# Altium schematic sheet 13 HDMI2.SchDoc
size 297 x 209 mm
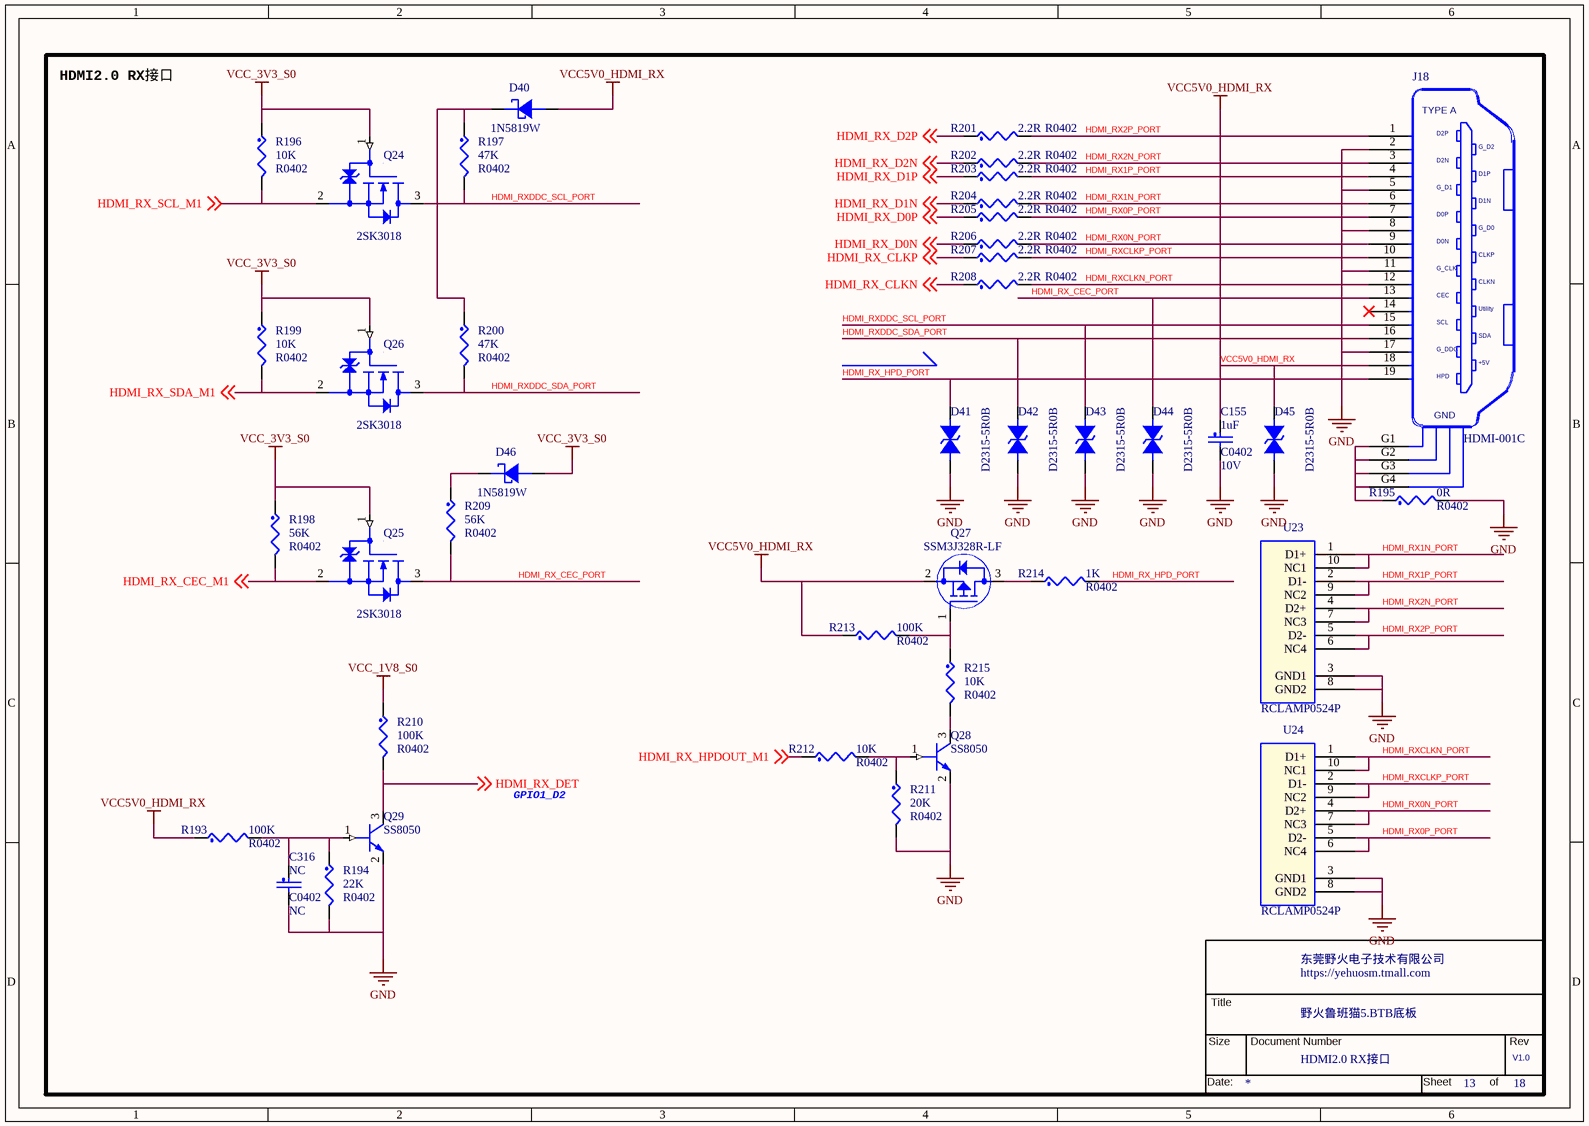
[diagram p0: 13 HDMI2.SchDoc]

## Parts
*  Doc: HDMI2.0 RX接口  RevCode: V1.0  Title: 野火鲁班猫5.BTB底板  OrgName: 东莞野火电子技术有限公司  Page Number: 13  Page Count: 18  (hidden comment: TitleBlock_YHSCH)  (graphical)
C155  1uF  Voltage: 10V  [C0402]
C316  NC  [C0402]
D40  1N5819W  [SOD-123]
D41  D2315-5R0B  [D0603/SMD]
D42  D2315-5R0B  [D0603/SMD]
D43  D2315-5R0B  [D0603/SMD]
D44  D2315-5R0B  [D0603/SMD]
D45  D2315-5R0B  [D0603/SMD]
D46  1N5819W  [SOD-123]
J18  HDMI-001C  [HDMI-SMD]
Q24  2SK3018  [SOT23]
Q25  2SK3018  [SOT23]
Q26  2SK3018  [SOT23]
Q27  SSM3J328R-LF  [SOT23]
Q28  SS8050  [SOT23]
Q29  SS8050  [SOT23]
R193  100K  [R0402]
R194  22K  [R0402]
R195  0R  [R0402]
R196  10K  [R0402]
R197  47K  [R0402]
R198  56K  [R0402]
R199  10K  [R0402]
R200  47K  [R0402]
R201  2.2R  [R0402]
R202  2.2R  [R0402]
R203  2.2R  [R0402]
R204  2.2R  [R0402]
R205  2.2R  [R0402]
R206  2.2R  [R0402]
R207  2.2R  [R0402]
R208  2.2R  [R0402]
R209  56K  [R0402]
R210  100K  [R0402]
R211  20K  [R0402]
R212  10K  [R0402]
R213  100K  [R0402]
R214  1K  [R0402]
R215  10K  [R0402]
U23  RCLAMP0524P  [USON_10]
U24  RCLAMP0524P  [USON_10]

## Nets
GND: C155.2 C316.2 D41.1 D42.1 D43.1 D44.1 D45.1 J18.2 J18.5 J18.8 J18.11 J18.17 Q28.2(EMITTER) Q29.2(EMITTER) R194.2 R195.2 R211.2 U23.3(GND1) U23.8(GND2) U24.3(GND1) U24.8(GND2)
VCC5V0_HDMI_RX: C155.1 D40.2 D45.2 J18.18 Q27.2(SOURCE) R193.1 R213.1
VCC_1V8_S0: R210.1
VCC_3V3_S0: D46.2 Q24.1(GATE) Q25.1(GATE) Q26.1(GATE) R196.1 R198.1 R199.1
HDMI_RX0N_PORT: J18.9 R206.2 U24.4(D2+) U24.7(NC3)
HDMI_RX0P_PORT: J18.7 R205.2 U24.5(D2-) U24.6(NC4)
HDMI_RX1N_PORT: J18.6 R204.2 U23.1(D1+) U23.10(NC1)
HDMI_RX1P_PORT: J18.4 R203.2 U23.2(D1-) U23.9(NC2)
HDMI_RX2N_PORT: J18.3 R202.2 U23.4(D2+) U23.7(NC3)
HDMI_RX2P_PORT: J18.1 R201.2 U23.5(D2-) U23.6(NC4)
HDMI_RX_CEC_M1: Q25.2(SOURCE) R198.2 ; off-sheet HDMI_RX_CEC_M1
HDMI_RX_CEC_PORT: D44.2 J18.13 Q25.3(DRAIN) R209.2
HDMI_RX_CLKN: R208.1 ; off-sheet HDMI_RX_CLKN
HDMI_RX_CLKP: R207.1 ; off-sheet HDMI_RX_CLKP
HDMI_RX_D0N: R206.1 ; off-sheet HDMI_RX_D0N
HDMI_RX_D0P: R205.1 ; off-sheet HDMI_RX_D0P
HDMI_RX_D1N: R204.1 ; off-sheet HDMI_RX_D1N
HDMI_RX_D1P: R203.1 ; off-sheet HDMI_RX_D1P
HDMI_RX_D2N: R202.1 ; off-sheet HDMI_RX_D2N
HDMI_RX_D2P: R201.1 ; off-sheet HDMI_RX_D2P
HDMI_RX_DET: Q29.3(COLLECTOR) R210.2 ; off-sheet HDMI_RX_DET
HDMI_RX_HPD_PORT: D41.2 J18.19 R214.2
HDMI_RX_HPDOUT_M1: R212.1 ; off-sheet HDMI_RX_HPDOUT_M1
HDMI_RX_SCL_M1: Q24.2(SOURCE) R196.2 ; off-sheet HDMI_RX_SCL_M1
HDMI_RX_SDA_M1: Q26.2(SOURCE) R199.2 ; off-sheet HDMI_RX_SDA_M1
HDMI_RXCLKN_PORT: J18.12 R208.2 U24.1(D1+) U24.10(NC1)
HDMI_RXCLKP_PORT: J18.10 R207.2 U24.2(D1-) U24.9(NC2)
HDMI_RXDDC_SCL_PORT: D43.2 J18.15 Q24.3(DRAIN) R197.2
HDMI_RXDDC_SDA_PORT: D42.2 J18.16 Q26.3(DRAIN) R200.2
NetC316_1: C316.1 Q29.1(BASE) R193.2 R194.1
NetD40_1: D40.1 R197.1 R200.1
NetD46_1: D46.1 R209.1
NetJ18_G1: J18.G1 J18.G2 J18.G3 J18.G4 R195.1
NetQ27_1: Q27.1(GATE) R213.2 R215.1
NetQ27_3: Q27.3(DRAIN) R214.1
NetQ28_1: Q28.1(BASE) R211.1 R212.2
NetQ28_3: Q28.3(COLLECTOR) R215.2

Not connected (* = marked no-connect by the designer): J18 14*

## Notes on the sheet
- HDMI2.0 RX接口
- GPIO1_D2

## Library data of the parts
* = TitleBlock_YHSCH: Cage Code: 1
C155 = CAP_NP: CLASS: DISCRETE; 生命周期: 量产; 价格: 0.01191; 规格书: 风华电容.pdf; 类别: 贴片电容0402; 品牌: 风华; 条码: EBF29060121; 规格编号: 0402X105K100NT; 规格: 贴片电容1uF 10% 10V X5R 0402
C316 = CAP_NP: CLASS: DISCRETE; 规格: 贴片电容NC 预留; 条码: EBF29060149; 类别: 贴片电容0402
D40 D46 = DIODE_SCHTKY: CLASS: IC; 丝印: SL; 生命周期: 量产; 价格: 0.175675; 规格书: 1N5819W.pdf; 类别: 贴片肖特基二极管; 品牌: 台湾迪嘉; 条码: EBF29140016; 规格: 肖特基二极管 直流反向耐压40V 平均整流电流1A 正向压降0.6V@1A SOD-123
D41-D45 = DIODE BI-DIR TRIG: PCB Footprint: esd0402; 备注: 通用; 生命周期: 量产; 规格书: 千虹_D2315-5R0B.pdf; 类别: 贴片ESD; 品牌: 千虹; 条码: EBFCIS240517170922; 规格: 防静电保护ESD二极管 反向工作电压5V 击穿电压7V 钳位电压10.5V 结电容Cj 0.3pF
J18 = HDMI-001C: VPN: 1166-2C105-211; Vendor: Comtek; OriginalSymbolOrigin: (-200,650); CLASS: IO; 生命周期: 量产; 规格书: HDMI-001C.pdf; 类别: HDMI连接器; 品牌: 讯普; 条码: EBF29040081; 规格: HDMI立式
Q24-Q26 = 2SK3018: CLASS: IC; 丝印: KN; 生命周期: 量产; 价格: 0.120725; 规格书: 长电科技-2SK3018.pdf; 类别: N-MOS; 品牌: 江苏长电; 条码: EBF29280009; 规格: N沟道MOS 导通电阻8Ω 电流10mA 0.8V可驱动
Q27 = MOSFET_P: CLASS: IC; 丝印: KFH-XXX; 生命周期: 量产; 价格: 0.447836; 规格书: SSM3J328R-LF.pdf; 类别: P-MOS; 品牌: 东芝; 条码: EBF29280008; 规格编号: SSM3J328R LF; 规格: P沟道MOS 导通电阻29.8mΩ 电流3A 1.5V可驱动
Q28 = NPN: CLASS: IC; 规格: 贴片三极管SS8050 集电极电流1.5A 额定功率300mW NPN; 条码: EBF29090001; 品牌: 江苏长电; 类别: 贴片三极管SOT-23; 规格书: 江苏长电-SS8050Y1.pdf; 价格: 0.086744; 生命周期: 量产; 丝印: Y1
Q29 = NPN: CLASS: IC; 丝印: Y1; 生命周期: 量产; 价格: 0.086744; 规格书: 江苏长电-SS8050Y1.pdf; 类别: 贴片三极管SOT-23; 品牌: 江苏长电; 条码: EBF29090001; 规格: 贴片三极管SS8050 集电极电流1.5A 额定功率300mW NPN
R193 R210 = RES: CLASS: DISCRETE; 规格: 贴片电阻100K 1% 1/16W 0402; 规格编号: RI0402L1003FT; 条码: EBF29070054; 品牌: 合科泰; 类别: 贴片电阻0402; 规格书: 合科泰-RI系列电阻.pdf; 生命周期: 量产
R194 = RES: CLASS: DISCRETE; 备注: 6750邮票孔; 价格: 0.003345; 生命周期: 量产; 规格书: 厚声-无铅厚膜电阻.pdf; 类别: 贴片电阻0402; 品牌: 厚声; 条码: EBFCIS230704154430; 规格编号: 0402WGF2202TCE; 规格: 贴片电阻22K 1% 1/16W 0402
R195 = RES: CLASS: DISCRETE; 规格: 贴片电阻0R 1% 1/16W 0402; 规格编号: RI0402L000FT; 条码: EBF29070049; 品牌: 合科泰; 类别: 贴片电阻0402; 规格书: 合科泰-RI系列电阻.pdf; 生命周期: 量产
R196 R199 R212 = RES: CLASS: DISCRETE; 生命周期: 量产; 价格: 0.002773; 规格书: 厚声-无铅厚膜电阻.pdf; 类别: 贴片电阻0402; 品牌: 厚声; 条码: EBF29070046; 规格编号: 0402WGF1002TCE; 规格: 贴片电阻10K 1% 1/16W 0402
R197 R200 = RES: CLASS: DISCRETE; 规格: 贴片电阻47K 1% 1/16W 0402; 规格编号: 0402WGF4702TCE; 条码: EBF29070247; 品牌: 厚声; 类别: 贴片电阻0402; 规格书: 厚声-无铅厚膜电阻.pdf; 生命周期: 量产
R198 R209 = RES: CLASS: DISCRETE; 生命周期: 量产; 价格: 0.002324; 规格书: 厚声-无铅厚膜电阻.pdf; 类别: 贴片电阻0402; 品牌: 厚声; 条码: EBF29070274; 规格编号: 0402WGF5602TCE; 规格: 贴片电阻56K 1% 1/16W 0402
R201-R208 = RES: CLASS: DISCRETE; 生命周期: 量产; 价格: 0.003072; 规格书: 厚声-无铅厚膜电阻.pdf; 类别: 贴片电阻0402; 品牌: 厚声; 条码: EBF29070280; 规格编号: 0402WGF220KTCE; 规格: 贴片电阻2.2R 1% 1/16W 0402
R211 = RES: CLASS: DISCRETE; 规格: 贴片电阻20K 1% 1/16W 0402; 规格编号: 0402WGF2002TCE; 条码: EBF29070223; 品牌: 厚声; 类别: 贴片电阻0402; 规格书: 厚声-无铅厚膜电阻.pdf; 价格: 0.002473; 生命周期: 量产
R213 = RES: CLASS: DISCRETE; 生命周期: 量产; 规格书: 合科泰-RI系列电阻.pdf; 类别: 贴片电阻0402; 品牌: 合科泰; 条码: EBF29070054; 规格编号: RI0402L1003FT; 规格: 贴片电阻100K 1% 1/16W 0402
R214 = RES: CLASS: DISCRETE; 规格: 贴片电阻1K 1% 1/16W 0402; 规格编号: RI0402L1001FT; 条码: EBF29070050; 品牌: 合科泰; 类别: 贴片电阻0402; 规格书: 合科泰-RI系列电阻.pdf; 生命周期: 量产
R215 = RES: CLASS: DISCRETE; 规格: 贴片电阻10K 1% 1/16W 0402; 规格编号: 0402WGF1002TCE; 条码: EBF29070046; 品牌: 厚声; 类别: 贴片电阻0402; 规格书: 厚声-无铅厚膜电阻.pdf; 价格: 0.002773; 生命周期: 量产
U23 = RCLAMP0524P: 生命周期: 量产; 价格: 0.185957; 规格书: 台舟-RCLAMP0524P.pdf; 类别: 贴片四路ESD; 品牌: 台舟; 条码: EBF29140046; 规格: TVS二极管 箝位电压17V 击穿电压8V 反向关断电压5V
U24 = RCLAMP0524P: 规格: TVS二极管 箝位电压17V 击穿电压8V 反向关断电压5V; 条码: EBF29140046; 品牌: 台舟; 类别: 贴片四路ESD; 规格书: 台舟-RCLAMP0524P.pdf; 价格: 0.185957; 生命周期: 量产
